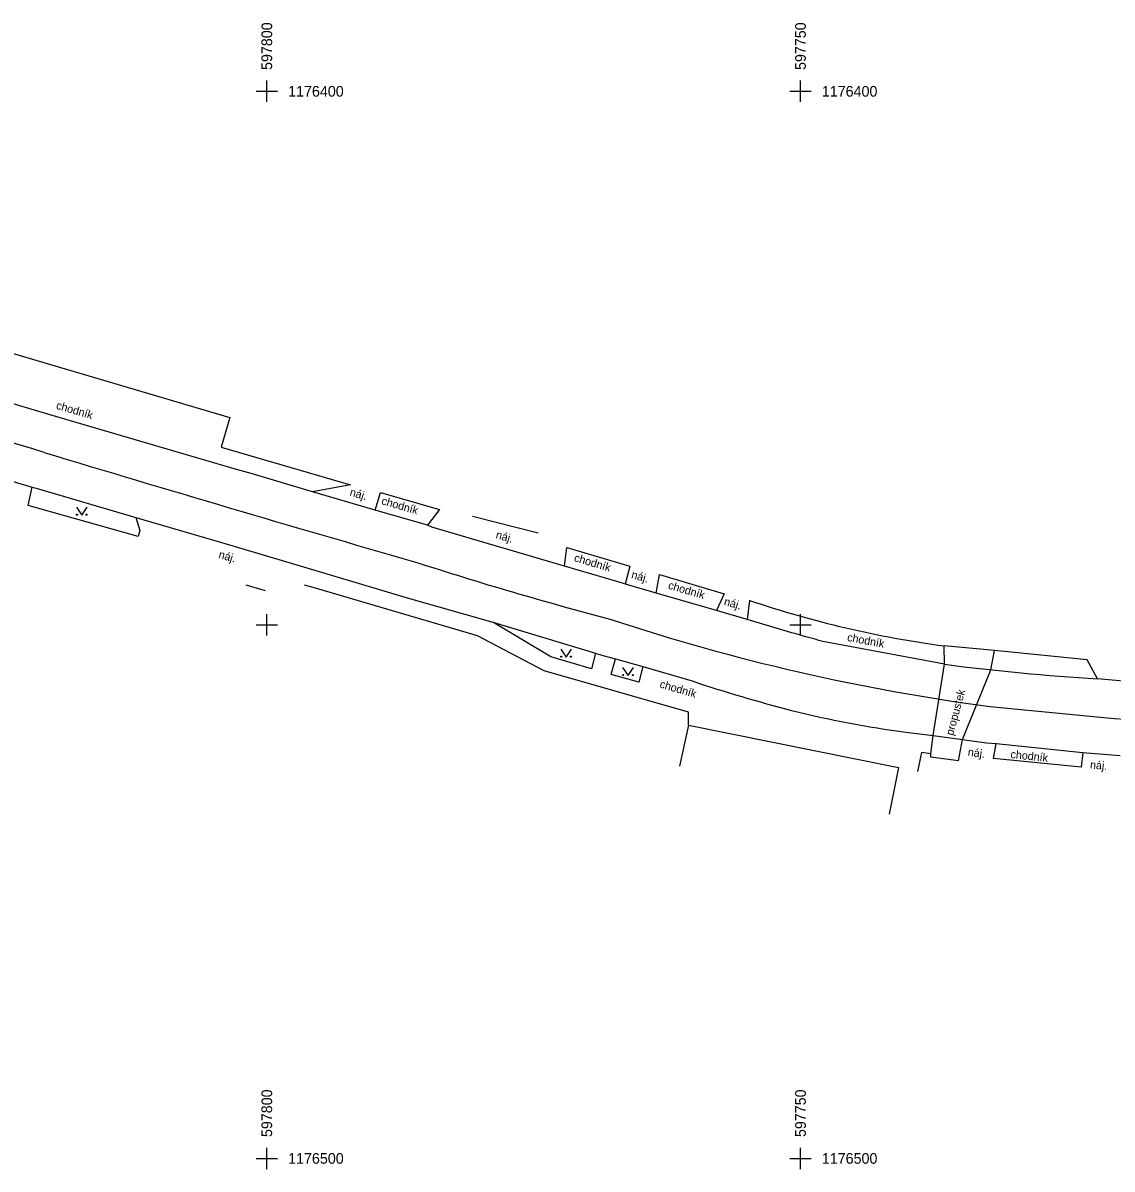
# Model space of a CAD drawing. Extents: x -598160 to -596067, y -1177005 to -1176344.
# Drawn here: x -597822.8 to -597720.8, y -1176501 to -1176393.6 of the extents above; entities that cross this region are included whole.
import ezdxf

# ---------------------------------------------------------------- set-up
doc = ezdxf.new("R2010")
doc.units = 0
for name, color, linetype in [('budova', 7, 'Continuous'), ('hektametrová síť', 7, 'Continuous'), ('obruba +0 cm', 7, 'Continuous'), ('obruba +12 cm', 7, 'Continuous'), ('obruba +3 cm', 7, 'Continuous'), ('popis ploch', 7, 'Continuous'), ('propustek', 7, 'Continuous'), ('rozhraní ploch', 7, 'Continuous'), ('vodorovné značení', 7, 'Continuous'), ('zeleň', 7, 'Continuous')]:
    doc.layers.add(name, color=color, linetype=linetype)

msp = doc.modelspace()

# ---------------------------------------------------------------- linework, layer by layer
at = {"layer": 'budova'}
for p, q in [((-597760.49, -1176459.39), (-597761.35, -1176463.24)), ((-597760.49, -1176459.39), (-597740.81, -1176463.36)), ((-597740.81, -1176463.36), (-597741.68, -1176467.75))]:
    msp.add_line(p, q, dxfattribs=at)
at = {"layer": 'hektametrová síť'}
for p, q in [((-597800, -1176401), (-597800, -1176399)), ((-597750, -1176401), (-597750, -1176399)), ((-597801, -1176400), (-597799, -1176400)), ((-597751, -1176400), (-597749, -1176400)), ((-597800, -1176451), (-597800, -1176449)), ((-597750, -1176451), (-597750, -1176449)), ((-597801, -1176450), (-597799, -1176450)), ((-597751, -1176450), (-597749, -1176450)), ((-597800, -1176501), (-597800, -1176499)), ((-597750, -1176501), (-597750, -1176499)), ((-597801, -1176500), (-597799, -1176500)), ((-597751, -1176500), (-597749, -1176500))]:
    msp.add_line(p, q, dxfattribs=at)
at = {"layer": 'obruba +0 cm'}
for p, q in [((-597820.21, -1176430.35), (-597830.01, -1176427.44)), ((-597802.84, -1176435.45), (-597820.21, -1176430.35)), ((-597801.46, -1176435.83), (-597802.84, -1176435.45)), ((-597825.3, -1176436.12), (-597821.97, -1176437.1)), ((-597789.86, -1176439.26), (-597795.73, -1176437.53)), ((-597812.28, -1176439.95), (-597804.34, -1176442.26)), ((-597784.55, -1176440.83), (-597784.95, -1176440.67)), ((-597772.12, -1176444.5), (-597784.55, -1176440.83)), ((-597804.34, -1176442.26), (-597796.26, -1176444.65)), ((-597763.51, -1176447.02), (-597766.4, -1176446.2)), ((-597755, -1176449.5), (-597757.88, -1176448.66)), ((-597769.21, -1176452.64), (-597768.52, -1176452.87)), ((-597768.52, -1176452.87), (-597767.34, -1176453.18)), ((-597716.68, -1176455.56), (-597722.16, -1176455.05)), ((-597734.81, -1176460.74), (-597732.57, -1176461.04)), ((-597732.57, -1176461.04), (-597731.68, -1176461.12)), ((-597723.56, -1176461.95), (-597720.06, -1176462.24))]:
    msp.add_line(p, q, dxfattribs=at)
for centre, radius, start, end in [((-600035.38, -1184635.66), 8497.77, 74.384251, 74.404552), ((-597718.66, -1176331.97), 130.08, 251.4054, 255.6823), ((-597727.94, -1176367.05), 93.8, 255.8771, 262.5346)]:
    msp.add_arc(centre, radius, start, end, dxfattribs=at)
at = {"layer": 'obruba +12 cm'}
for p, q in [((-597795.73, -1176437.53), (-597801.46, -1176435.83)), ((-597821.97, -1176437.1), (-597821.61, -1176437.2)), ((-597821.61, -1176437.2), (-597812.28, -1176439.95)), ((-597784.95, -1176440.67), (-597789.86, -1176439.26)), ((-597767, -1176446.01), (-597772.12, -1176444.5)), ((-597766.4, -1176446.2), (-597767, -1176446.01)), ((-597757.88, -1176448.66), (-597763.51, -1176447.02)), ((-597778.83, -1176449.76), (-597769.21, -1176452.64)), ((-597750.81, -1176450.74), (-597755, -1176449.5)), ((-597736.5, -1176453.69), (-597747.91, -1176451.55)), ((-597767.34, -1176453.18), (-597764.78, -1176453.91)), ((-597764.78, -1176453.91), (-597760.14, -1176455.26)), ((-597740.13, -1176460.05), (-597737.57, -1176460.37)), ((-597737.57, -1176460.37), (-597734.81, -1176460.74)), ((-597731.68, -1176461.12), (-597723.56, -1176461.95))]:
    msp.add_line(p, q, dxfattribs=at)
msp.add_arc((-597710.34, -1176254.18), 201.22, 262.5311, 266.6335, dxfattribs=at)
at = {"layer": 'obruba +3 cm'}
for p, q in [((-597796.26, -1176444.65), (-597786.64, -1176447.52)), ((-597786.64, -1176447.52), (-597778.83, -1176449.76))]:
    msp.add_line(p, q, dxfattribs=at)
at = {"layer": 'propustek'}
for p, q in [((-597736.5, -1176453.69), (-597736.54, -1176451.97)), ((-597732.17, -1176454.21), (-597731.82, -1176452.4)), ((-597737.57, -1176460.37), (-597736.5, -1176453.69)), ((-597734.81, -1176460.74), (-597732.17, -1176454.21)), ((-597737.8, -1176462.09), (-597737.57, -1176460.37)), ((-597735.2, -1176462.73), (-597734.81, -1176460.74))]:
    msp.add_line(p, q, dxfattribs=at)
at = {"layer": 'rozhraní ploch'}
for p, q in [((-597829.12, -1176423), (-597803.47, -1176430.57)), ((-597803.47, -1176430.57), (-597804.26, -1176433.36)), ((-597804.26, -1176433.36), (-597792.15, -1176436.88)), ((-597792.15, -1176436.88), (-597795.73, -1176437.53)), ((-597822.34, -1176438.8), (-597821.97, -1176437.1)), ((-597789.86, -1176439.26), (-597789.36, -1176437.59)), ((-597789.36, -1176437.59), (-597783.81, -1176439.2)), ((-597812.05, -1176441.72), (-597822.34, -1176438.8)), ((-597812.28, -1176439.95), (-597811.89, -1176441.16)), ((-597783.81, -1176439.2), (-597784.95, -1176440.67)), ((-597780.74, -1176439.8), (-597774.58, -1176441.39)), ((-597811.89, -1176441.16), (-597812.05, -1176441.72)), ((-597772.12, -1176444.5), (-597771.88, -1176442.75)), ((-597771.88, -1176442.75), (-597765.98, -1176444.49)), ((-597765.98, -1176444.49), (-597766.41, -1176446.2)), ((-597763.51, -1176447.02), (-597763.22, -1176445.29)), ((-597763.22, -1176445.29), (-597757.15, -1176447.09)), ((-597800.13, -1176446.82), (-597801.92, -1176446.28)), ((-597795.67, -1176446.5), (-597796.47, -1176446.27)), ((-597780.27, -1176451.02), (-597795.67, -1176446.5)), ((-597757.15, -1176447.09), (-597757.88, -1176448.66)), ((-597754.79, -1176447.7), (-597755, -1176449.5)), ((-597773.38, -1176453), (-597778.83, -1176449.76)), ((-597774.02, -1176454.32), (-597780.27, -1176451.02)), ((-597731.82, -1176452.4), (-597736.54, -1176451.97)), ((-597769.57, -1176454.11), (-597773.38, -1176453)), ((-597769.21, -1176452.64), (-597769.57, -1176454.11)), ((-597723.13, -1176453.28), (-597731.82, -1176452.4)), ((-597767.74, -1176454.66), (-597767.34, -1176453.18)), ((-597764.78, -1176453.91), (-597765.16, -1176455.37)), ((-597722.16, -1176455.05), (-597723.13, -1176453.28)), ((-597760.49, -1176458.18), (-597774.02, -1176454.32)), ((-597765.16, -1176455.37), (-597767.74, -1176454.66)), ((-597760.49, -1176459.39), (-597760.49, -1176458.18)), ((-597731.91, -1176462.51), (-597731.68, -1176461.12)), ((-597738.66, -1176461.95), (-597739.05, -1176463.74)), ((-597737.8, -1176462.09), (-597738.66, -1176461.95)), ((-597737.8, -1176462.41), (-597737.8, -1176462.09)), ((-597735.2, -1176462.73), (-597737.8, -1176462.41)), ((-597723.69, -1176463.33), (-597731.91, -1176462.51)), ((-597723.56, -1176461.95), (-597723.69, -1176463.33))]:
    msp.add_line(p, q, dxfattribs=at)
msp.add_arc((-597723.78, -1176356.32), 96.5, 251.2582, 262.4043, dxfattribs=at)
at = {"layer": 'vodorovné značení'}
for centre, radius, start, end in [((-598414.67, -1178378.53), 2033.33, 73.02006, 74.01831), ((-596983.49, -1173662.1), 2895.47, 253.18984, 253.90601), ((-597678.84, -1176112.5), 348.52, 252.0678, 255.2206), ((-597706.66, -1176265.25), 194.1, 251.6552, 262.424), ((-597628.21, -1175428.59), 1034.31, 264.22718, 265.95582)]:
    msp.add_arc(centre, radius, start, end, dxfattribs=at)
at = {"layer": 'zeleň'}
for points in [[(-597817.82, -1176438.97), (-597817.32, -1176439.72), (-597816.82, -1176438.97)], [(-597772.46, -1176452.28), (-597771.96, -1176453.03), (-597771.46, -1176452.28)], [(-597766.66, -1176454.01), (-597766.16, -1176454.76), (-597765.66, -1176454.01)]]:
    msp.add_lwpolyline(points, dxfattribs=at)
for centre in [(-597817.78, -1176439.67), (-597816.88, -1176439.67), (-597772.41, -1176452.98), (-597771.51, -1176452.98), (-597766.61, -1176454.71), (-597765.71, -1176454.71)]:
    msp.add_circle(centre, 0.05, dxfattribs=at)

# ---------------------------------------------------------------- texts
at = {"layer": 'hektametrová síť'}
for s, p in [('597800', (-597799.5, -1176398)), ('597750', (-597749.5, -1176398)), ('597800', (-597799.5, -1176498)), ('597750', (-597749.5, -1176498))]:
    msp.add_text(s, height=1, rotation=90, dxfattribs=at).set_placement(p)
for s, p in [('1176400', (-597798, -1176400.5)), ('1176400', (-597748, -1176400.5)), ('1176500', (-597798, -1176500.5)), ('1176500', (-597748, -1176500.5))]:
    msp.add_text(s, height=1, dxfattribs=at).set_placement(p)
at = {"layer": 'popis ploch'}
for s, rotation, p in [('chodník', 343.6373, (-597819.79, -1176429.74)), ('náj.', 343.5788, (-597792.28, -1176437.87)), ('chodník', 343.9776, (-597789.32, -1176438.69)), ('náj.', 343.5506, (-597778.6, -1176441.86)), ('náj.', 343.5222, (-597804.57, -1176443.71)), ('chodník', 343.5681, (-597771.27, -1176444.02)), ('náj.', 344.1594, (-597765.9, -1176445.61)), ('chodník', 343.7593, (-597762.46, -1176446.6)), ('náj.', 343.7398, (-597757.22, -1176448.12)), ('chodník', 349.3773, (-597745.67, -1176451.5)), ('chodník', 343.7777, (-597763.25, -1176455.86)), ('propustek', 74.9816, (-597735.7, -1176460.42)), ('náj.', 352.3719, (-597734.36, -1176462.26)), ('chodník', 354.1637, (-597730.35, -1176462.48)), ('náj.', 355.2635, (-597722.9, -1176463.46))]:
    msp.add_text(s, height=0.75, rotation=rotation, dxfattribs=at).set_placement(p)

doc.saveas('drawing.dxf')
